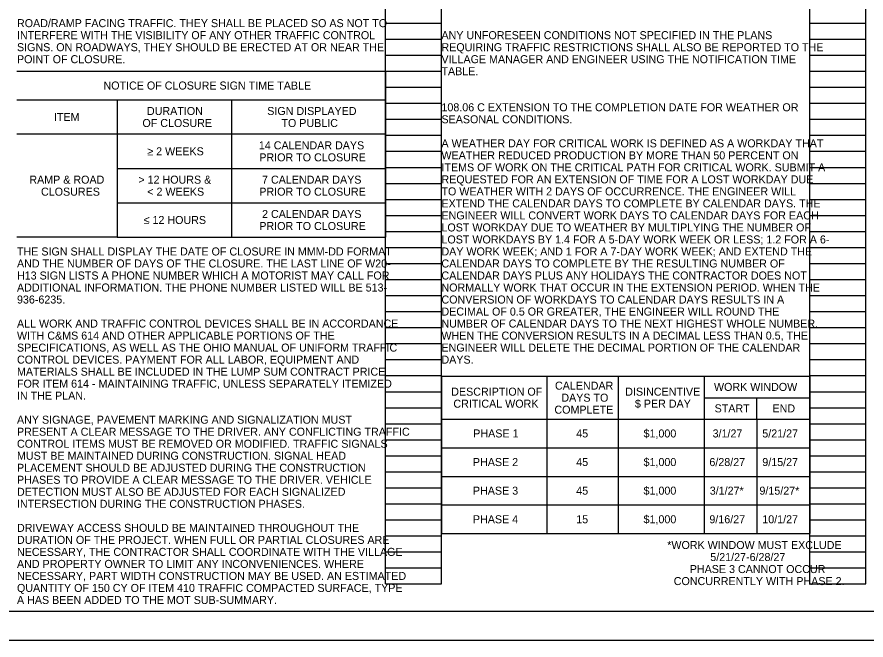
# Model space of a CAD drawing. Extents: x -6.4 to 60.5, y 0 to 37.1.
# Drawn here: x 9.82 to 24.66, y 0 to 10.89 of the extents above; entities that cross this region are included whole.
import ezdxf

# ---------------------------------------------------------------- set-up
doc = ezdxf.new("R2010")
doc.units = 0
for name, color, linetype in [('SH_Border', 7, 'Continuous'), ('SH_Cut_Line', 7, 'Continuous'), ('SH_Data', 7, 'Continuous'), ('SH_Text', 7, 'Continuous')]:
    doc.layers.add(name, color=color, linetype=linetype)

msp = doc.modelspace()

# ---------------------------------------------------------------- linework, layer by layer
at = {"layer": 'SH_Border'}
msp.add_lwpolyline([(1.5, 21.5), (33.5, 21.5), (33.5, 0.5), (1.5, 0.5)], close=True, dxfattribs=at)
at = {"layer": 'SH_Cut_Line'}
msp.add_lwpolyline([(0, 0), (34, 0), (34, 22), (0, 22)], close=True, dxfattribs=at)
at = {"layer": 'SH_Data'}
for p, q in [((16.26, 0.98), (16.26, 21.14)), ((17.24, 0.98), (17.24, 21.14)), ((23.68, 0.98), (23.68, 21.14)), ((24.66, 0.98), (24.66, 21.14)), ((16.26, 10.78), (17.24, 10.78)), ((23.68, 10.78), (24.66, 10.78)), ((16.26, 10.5), (17.24, 10.5)), ((23.68, 10.5), (24.66, 10.5)), ((16.26, 10.22), (17.24, 10.22)), ((23.68, 10.22), (24.66, 10.22)), ((16.26, 9.94), (17.24, 9.94)), ((23.68, 9.94), (24.66, 9.94)), ((16.26, 9.66), (17.24, 9.66)), ((23.68, 9.66), (24.66, 9.66)), ((16.26, 9.38), (17.24, 9.38)), ((23.68, 9.38), (24.66, 9.38)), ((16.26, 9.1), (17.24, 9.1)), ((23.68, 9.1), (24.66, 9.1)), ((16.26, 8.82), (17.24, 8.82)), ((23.68, 8.82), (24.66, 8.82)), ((16.26, 8.54), (17.24, 8.54)), ((23.68, 8.54), (24.66, 8.54)), ((16.26, 8.26), (17.24, 8.26)), ((23.68, 8.26), (24.66, 8.26)), ((16.26, 7.98), (17.24, 7.98)), ((23.68, 7.98), (24.66, 7.98)), ((16.26, 7.7), (17.24, 7.7)), ((23.68, 7.7), (24.66, 7.7)), ((16.26, 7.42), (17.24, 7.42)), ((23.68, 7.42), (24.66, 7.42)), ((16.26, 7.14), (17.24, 7.14)), ((23.68, 7.14), (24.66, 7.14)), ((16.26, 6.86), (17.24, 6.86)), ((23.68, 6.86), (24.66, 6.86)), ((16.26, 6.58), (17.24, 6.58)), ((23.68, 6.58), (24.66, 6.58)), ((16.26, 6.3), (17.24, 6.3)), ((23.68, 6.3), (24.66, 6.3)), ((16.26, 6.02), (17.24, 6.02)), ((23.68, 6.02), (24.66, 6.02)), ((16.26, 5.74), (17.24, 5.74)), ((23.68, 5.74), (24.66, 5.74)), ((16.26, 5.46), (17.24, 5.46)), ((23.68, 5.46), (24.66, 5.46)), ((16.26, 5.18), (17.24, 5.18)), ((23.68, 5.18), (24.66, 5.18)), ((16.26, 4.9), (17.24, 4.9)), ((23.68, 4.9), (24.66, 4.9)), ((16.26, 4.62), (17.24, 4.62)), ((23.68, 4.62), (24.66, 4.62)), ((16.26, 4.34), (17.24, 4.34)), ((23.68, 4.34), (24.66, 4.34)), ((16.26, 4.06), (17.24, 4.06)), ((23.68, 4.06), (24.66, 4.06)), ((16.26, 3.78), (17.24, 3.78)), ((23.68, 3.78), (24.66, 3.78)), ((16.26, 3.5), (17.24, 3.5)), ((23.68, 3.5), (24.66, 3.5)), ((16.26, 3.22), (17.24, 3.22)), ((23.68, 3.22), (24.66, 3.22)), ((16.26, 2.94), (17.24, 2.94)), ((23.68, 2.94), (24.66, 2.94)), ((16.26, 2.66), (17.24, 2.66)), ((23.68, 2.66), (24.66, 2.66)), ((16.26, 2.38), (17.24, 2.38)), ((23.68, 2.38), (24.66, 2.38)), ((16.26, 2.1), (17.24, 2.1)), ((23.68, 2.1), (24.66, 2.1)), ((16.26, 1.82), (17.24, 1.82)), ((23.68, 1.82), (24.66, 1.82)), ((16.26, 1.54), (17.24, 1.54)), ((23.68, 1.54), (24.66, 1.54)), ((16.26, 1.26), (17.24, 1.26)), ((23.68, 1.26), (24.66, 1.26)), ((16.26, 0.98), (17.24, 0.98)), ((23.68, 0.98), (24.66, 0.98))]:
    msp.add_line(p, q, dxfattribs=at)
at = {"layer": 'SH_Text'}
for p, q in [((9.82, 9.94), (16.26, 9.94)), ((16.26, 9.94), (16.26, 9.44)), ((9.82, 9.44), (16.26, 9.44)), ((11.57, 9.44), (11.57, 8.84)), ((13.57, 9.44), (13.57, 8.84)), ((16.26, 9.44), (16.26, 8.84)), ((11.57, 8.84), (9.82, 8.84)), ((11.57, 8.84), (11.57, 7.04)), ((13.57, 8.84), (11.57, 8.84)), ((13.57, 8.84), (13.57, 8.24)), ((16.26, 8.84), (13.57, 8.84)), ((16.26, 8.84), (16.26, 8.24)), ((11.57, 8.24), (13.57, 8.24)), ((13.57, 8.24), (16.26, 8.24)), ((13.57, 8.24), (13.57, 7.64)), ((16.26, 8.24), (16.26, 7.64)), ((11.57, 7.64), (13.57, 7.64)), ((13.57, 7.64), (16.26, 7.64)), ((13.57, 7.64), (13.57, 7.04)), ((16.26, 7.64), (16.26, 7.04)), ((11.57, 7.04), (9.82, 7.04)), ((11.57, 7.04), (13.57, 7.04)), ((13.57, 7.04), (16.26, 7.04)), ((17.24, 4.61), (17.24, 3.86)), ((19.08, 4.61), (19.08, 3.86)), ((20.33, 4.61), (20.33, 3.86)), ((21.83, 4.61), (21.83, 3.86)), ((23.68, 4.61), (23.68, 3.86)), ((21.83, 4.235), (23.68, 4.235)), ((22.755, 3.86), (22.755, 4.235)), ((17.24, 3.86), (17.24, 3.36)), ((19.08, 3.86), (19.08, 3.36)), ((20.33, 3.86), (20.33, 3.36)), ((21.83, 3.86), (21.83, 3.36)), ((22.755, 3.86), (22.755, 3.36)), ((23.68, 3.86), (23.68, 3.36)), ((17.24, 3.36), (17.24, 2.86)), ((19.08, 3.36), (19.08, 2.86)), ((20.33, 3.36), (20.33, 2.86)), ((21.83, 3.36), (21.83, 2.86)), ((22.755, 3.36), (22.755, 2.86)), ((23.68, 3.36), (23.68, 2.86)), ((17.24, 2.86), (17.24, 2.36)), ((19.08, 2.86), (19.08, 2.36)), ((20.33, 2.86), (20.33, 2.36)), ((21.83, 2.86), (21.83, 2.36)), ((22.755, 2.86), (22.755, 2.36)), ((23.68, 2.86), (23.68, 2.36)), ((17.24, 2.36), (17.24, 1.86)), ((19.08, 2.36), (19.08, 1.86)), ((20.33, 2.36), (20.33, 1.86)), ((21.83, 2.36), (21.83, 1.86)), ((22.755, 2.36), (22.755, 1.86)), ((23.68, 2.36), (23.68, 1.86))]:
    msp.add_line(p, q, dxfattribs=at)
for points in [[(17.24, 4.61), (19.08, 4.61), (20.33, 4.61), (21.83, 4.61), (23.68, 4.61)], [(17.24, 3.86), (19.08, 3.86), (20.33, 3.86), (21.83, 3.86), (22.755, 3.86), (23.68, 3.86)], [(17.24, 3.36), (19.08, 3.36), (20.33, 3.36), (21.83, 3.36), (22.755, 3.36), (23.68, 3.36)], [(17.24, 2.86), (19.08, 2.86), (20.33, 2.86), (21.83, 2.86), (22.755, 2.86), (23.68, 2.86)], [(17.24, 2.36), (19.08, 2.36), (20.33, 2.36), (21.83, 2.36), (22.755, 2.36), (23.68, 2.36)], [(17.24, 2.36), (19.08, 2.36), (20.33, 2.36), (21.83, 2.36), (22.755, 2.36), (23.68, 2.36)], [(17.24, 1.86), (19.08, 1.86), (20.33, 1.86), (21.83, 1.86), (22.755, 1.86), (23.68, 1.86)]]:
    msp.add_lwpolyline(points, dxfattribs=at)

# ---------------------------------------------------------------- texts
for s, p in [('ROAD/RAMP FACING TRAFFIC. THEY SHALL BE PLACED SO AS NOT TO ', (9.82, 10.71)), ('INTERFERE WITH THE VISIBILITY OF ANY OTHER TRAFFIC CONTROL ', (9.82, 10.5)), ('ANY UNFORESEEN CONDITIONS NOT SPECIFIED IN THE PLANS ', (17.24, 10.5)), ('SIGNS. ON ROADWAYS, THEY SHOULD BE ERECTED AT OR NEAR THE ', (9.82, 10.29)), ('REQUIRING TRAFFIC RESTRICTIONS SHALL ALSO BE REPORTED TO THE ', (17.24, 10.29)), ('POINT OF CLOSURE.', (9.82, 10.08)), ('VILLAGE MANAGER AND ENGINEER USING THE NOTIFICATION TIME ', (17.24, 10.08)), ('TABLE.', (17.24, 9.87)), ('NOTICE OF CLOSURE SIGN TIME TABLE', (11.332, 9.62)), ('108.06 C EXTENSION TO THE COMPLETION DATE FOR WEATHER OR ', (17.24, 9.24)), ('ITEM', (10.466, 9.07)), ('DURATION', (12.092, 9.175)), ('SIGN DISPLAYED', (14.195, 9.175)), ('OF CLOSURE', (12.013, 8.965)), ('TO PUBLIC', (14.443, 8.965)), ('SEASONAL CONDITIONS.', (17.24, 9.03)), ('≥ 2 WEEKS', (12.098, 8.47)), ('14 CALENDAR DAYS', (14.048, 8.575)), ('A WEATHER DAY FOR CRITICAL WORK IS DEFINED AS A WORKDAY THAT ', (17.24, 8.61)), ('PRIOR TO CLOSURE', (14.056, 8.365)), ('WEATHER REDUCED PRODUCTION BY MORE THAN 50 PERCENT ON ', (17.24, 8.4)), ('ITEMS OF WORK ON THE CRITICAL PATH FOR CRITICAL WORK. SUBMIT A ', (17.24, 8.19)), ('RAMP & ROAD', (10.036, 7.975)), ('> 12 HOURS &', (11.942, 7.975)), ('7 CALENDAR DAYS', (14.104, 7.975)), ('REQUESTED FOR AN EXTENSION OF TIME FOR A LOST WORKDAY DUE ', (17.24, 7.98)), ('CLOSURES', (10.24, 7.765)), ('< 2 WEEKS', (12.098, 7.765)), ('PRIOR TO CLOSURE', (14.056, 7.765)), ('TO WEATHER WITH 2 DAYS OF OCCURRENCE. THE ENGINEER WILL ', (17.24, 7.77)), ('EXTEND THE CALENDAR DAYS TO COMPLETE BY CALENDAR DAYS. THE ', (17.24, 7.56)), ('2 CALENDAR DAYS', (14.104, 7.375)), ('ENGINEER WILL CONVERT WORK DAYS TO CALENDAR DAYS FOR EACH ', (17.24, 7.35)), ('≤ 12 HOURS', (12.034, 7.27)), ('PRIOR TO CLOSURE', (14.056, 7.165)), ('LOST WORKDAY DUE TO WEATHER BY MULTIPLYING THE NUMBER OF ', (17.24, 7.14)), ('LOST WORKDAYS BY 1.4 FOR A 5-DAY WORK WEEK OR LESS; 1.2 FOR A 6-', (17.24, 6.93)), ('THE SIGN SHALL DISPLAY THE DATE OF CLOSURE IN MMM-DD FORMAT ', (9.82, 6.72)), ('DAY WORK WEEK; AND 1 FOR A 7-DAY WORK WEEK; AND EXTEND THE ', (17.24, 6.72)), ('AND THE NUMBER OF DAYS OF THE CLOSURE. THE LAST LINE OF W20-', (9.82, 6.51)), ('CALENDAR DAYS TO COMPLETE BY THE RESULTING NUMBER OF ', (17.24, 6.51)), ('H13 SIGN LISTS A PHONE NUMBER WHICH A MOTORIST MAY CALL FOR ', (9.82, 6.3)), ('CALENDAR DAYS PLUS ANY HOLIDAYS THE CONTRACTOR DOES NOT ', (17.24, 6.3)), ('ADDITIONAL INFORMATION. THE PHONE NUMBER LISTED WILL BE 513-', (9.82, 6.09)), ('NORMALLY WORK THAT OCCUR IN THE EXTENSION PERIOD. WHEN THE ', (17.24, 6.09)), ('936-6235.', (9.82, 5.88)), ('CONVERSION OF WORKDAYS TO CALENDAR DAYS RESULTS IN A ', (17.24, 5.88)), ('DECIMAL OF 0.5 OR GREATER, THE ENGINEER WILL ROUND THE ', (17.24, 5.67)), ('ALL WORK AND TRAFFIC CONTROL DEVICES SHALL BE IN ACCORDANCE ', (9.82, 5.46)), ('NUMBER OF CALENDAR DAYS TO THE NEXT HIGHEST WHOLE NUMBER. ', (17.24, 5.46)), ('WITH C&MS 614 AND OTHER APPLICABLE PORTIONS OF THE ', (9.82, 5.25)), ('WHEN THE CONVERSION RESULTS IN A DECIMAL LESS THAN 0.5, THE ', (17.24, 5.25)), ('SPECIFICATIONS, AS WELL AS THE OHIO MANUAL OF UNIFORM TRAFFIC ', (9.82, 5.04)), ('ENGINEER WILL DELETE THE DECIMAL PORTION OF THE CALENDAR ', (17.24, 5.04)), ('CONTROL DEVICES. PAYMENT FOR ALL LABOR, EQUIPMENT AND ', (9.82, 4.83)), ('DAYS.', (17.24, 4.83)), ('MATERIALS SHALL BE INCLUDED IN THE LUMP SUM CONTRACT PRICE ', (9.82, 4.62)), ('FOR ITEM 614 - MAINTAINING TRAFFIC, UNLESS SEPARATELY ITEMIZED ', (9.82, 4.41)), ('CALENDAR ', (19.225, 4.375)), ('WORK WINDOW', (22.004, 4.353)), ('IN THE PLAN.', (9.82, 4.2)), ('DESCRIPTION OF ', (17.411, 4.27)), ('DAYS TO ', (19.336, 4.165)), ('DISINCENTIVE ', (20.453, 4.27)), ('CRITICAL WORK', (17.449, 4.06)), ('$ PER DAY', (20.622, 4.06)), ('COMPLETE', (19.215, 3.955)), ('START', (22.015, 3.978)), ('END', (23.027, 3.978)), ('ANY SIGNAGE, PAVEMENT MARKING AND SIGNALIZATION MUST ', (9.82, 3.78)), ('PRESENT A CLEAR MESSAGE TO THE DRIVER. ANY CONFLICTING TRAFFIC ', (9.82, 3.57)), ('PHASE 1', (17.796, 3.54)), ('45', (19.596, 3.54)), ('$1,000', (20.773, 3.54)), ('3/1/27', (21.98, 3.54)), ('5/21/27', (22.849, 3.54)), ('CONTROL ITEMS MUST BE REMOVED OR MODIFIED. TRAFFIC SIGNALS ', (9.82, 3.36)), ('MUST BE MAINTAINED DURING CONSTRUCTION. SIGNAL HEAD ', (9.82, 3.15)), ('PHASE 2', (17.79, 3.04)), ('45', (19.596, 3.04)), ('$1,000', (20.773, 3.04)), ('6/28/27', (21.924, 3.04)), ('9/15/27', (22.849, 3.04)), ('PLACEMENT SHOULD BE ADJUSTED DURING THE CONSTRUCTION ', (9.82, 2.94)), ('PHASES TO PROVIDE A CLEAR MESSAGE TO THE DRIVER. VEHICLE ', (9.82, 2.73)), ('PHASE 3', (17.79, 2.54)), ('45', (19.596, 2.54)), ('$1,000', (20.773, 2.54)), ('3/1/27*', (21.93, 2.54)), ('9/15/27*', (22.799, 2.54)), ('DETECTION MUST ALSO BE ADJUSTED FOR EACH SIGNALIZED ', (9.82, 2.52)), ('INTERSECTION DURING THE CONSTRUCTION PHASES. ', (9.82, 2.31)), ('PHASE 4', (17.79, 2.04)), ('15', (19.596, 2.04)), ('$1,000', (20.773, 2.04)), ('9/16/27', (21.924, 2.04)), ('10/1/27', (22.849, 2.04)), ('DRIVEWAY ACCESS SHOULD BE MAINTAINED THROUGHOUT THE ', (9.82, 1.89)), ('DURATION OF THE PROJECT. WHEN FULL OR PARTIAL CLOSURES ARE ', (9.82, 1.68)), ('*WORK WINDOW MUST EXCLUDE ', (21.187, 1.59)), ('NECESSARY, THE CONTRACTOR SHALL COORDINATE WITH THE VILLAGE ', (9.82, 1.47)), ('5/21/27-6/28/27', (21.94, 1.38)), ('AND PROPERTY OWNER TO LIMIT ANY INCONVENIENCES. WHERE ', (9.82, 1.26)), ('NECESSARY, PART WIDTH CONSTRUCTION MAY BE USED. AN ESTIMATED ', (9.82, 1.05)), ('PHASE 3 CANNOT OCCUR ', (21.581, 1.17)), ('CONCURRENTLY WITH PHASE 2. ', (21.301, 0.96)), ('QUANTITY OF 150 CY OF ITEM 410 TRAFFIC COMPACTED SURFACE, TYPE ', (9.82, 0.84)), ('A HAS BEEN ADDED TO THE MOT SUB-SUMMARY. ', (9.82, 0.63))]:
    msp.add_text(s, height=0.14, dxfattribs=at).set_placement(p)

doc.saveas('drawing.dxf')
